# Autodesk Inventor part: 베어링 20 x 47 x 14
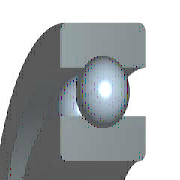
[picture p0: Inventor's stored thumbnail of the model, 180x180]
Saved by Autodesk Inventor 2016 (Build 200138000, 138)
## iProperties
IsCustomPart: 1
Created: 2012-02
Part Number: 베어링 20 x 47 x 14
Material: 강철, 연강
Description: 깊은 그루브 볼 베어링
Document SubType Name: Modeling
Standard: KS B 2023
Designer: mduedu
Standards Organization: KS
Language: ko-KR
Size Designation: 6204 - 20 x 47 x 14
Categories: <MemberInstance><Categories><Category DisplayName="샤프트 부품" InternalName="7f7aeb1f-a693-4053-b835-cee3144e0d98" Mnemonic="SHFT"><Category DisplayName="베어링" Inter
Density: 7.86 g/cm^3
Mass: 104.255 g
Surface Area: 87.8912 cm^2
Volume: 13.264 cm^3
Appearance: 노란색
Author: mduedu
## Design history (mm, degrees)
sketch "스케치" dims "d0" = 7.02 (= -0.26 x WD + 0.26 x BD)
  geometry: L1 (3.49, 16.75)-(10.51, 16.75); L2 (7, 16.75)-(7, 13.24); L3 (7, 16.75)-(7, 20.26); L4 (4.392, 14.401)-(0, 14.401); L5 (0, 10)-(14, 10); L6 (4.392, 19.099)-(0, 19.099); L7 (0, 23.5)-(14, 23.5); L8 (14, 10)-(14, 14.401); L9 (9.608, 14.401)-(14, 14.401); L10 (9.608, 19.099)-(14, 19.099); L11 (14, 23.5)-(14, 19.099); L12 (-1.4, 0)-(8.4, 0) reference; L13 (0, -0.3)-(0, 5.3) reference
  constraints: 22 end point, 4 point on line, 2 collinear, 2 perpendicular, 2 symmetric about line, 1 midpoint, 1 parallel, 14 other
  dimensions: "d9" = 20 diameter of L5 L12 (= WD); "d11" = 47 diameter of L7 L12 (= BD); "d12" = 14 distance between parallel lines of L8 L13 (= KB); "d13" = 28.802 diameter of L9 L12 (= 0.326 x BD + 0.674 x WD)
revolve "본체" stored, may be unused: angle "d6" = 90 deg
revolve "볼" stored, may be unused: angle "d7" = 90 deg
pattern_circular "IDS_ARRAYBALL[SIMPL:T]" dims angle "d3" = 360 deg
body "Solid1"
fillet "모깎기1" dims "d1" = 1 (= KRS)
other parameters: "WD" = 20 [user parameter; used in 5 equation terms], "BD" = 47 [user parameter; used in 5 equation terms], "KB" = 14 [user parameter; used in 1 equation term], "KRS" = 1 [user parameter; used in 1 equation term], "d4" = 0, "d5" = 0, "d8" = 0, "d14" = 0, "d15" = 0, "BBA" = 0 [user parameter], "BC0" = 6550000 [user parameter], "BC" = 1.27e+07 [user parameter], "BR" = 23.5 (= 0.5 x BD) [user parameter]
